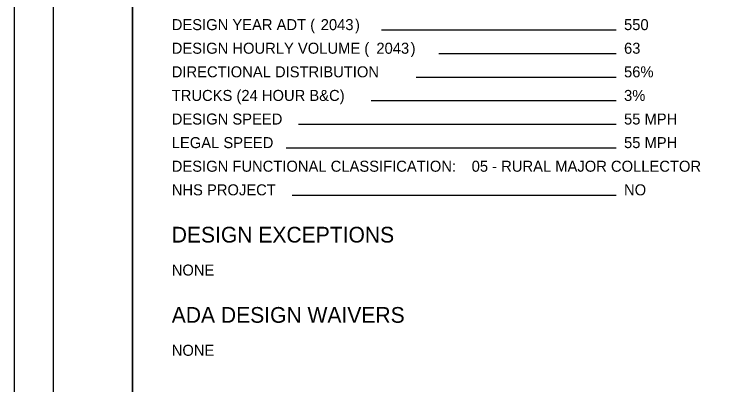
# Model space of a CAD drawing. Extents: x -6.4 to 34, y -1.2 to 22.
# Drawn here: x 0 to 9.02, y 5.69 to 10.4 of the extents above; entities that cross this region are included whole.
import ezdxf

# ---------------------------------------------------------------- set-up
doc = ezdxf.new("R2010")
doc.units = 0
for name, color, linetype in [('GM_X_County', 7, 'Continuous'), ('GM_X_Section', 7, 'Continuous'), ('GM_X_Township', 7, 'Continuous')]:
    doc.layers.add(name, color=color, linetype=linetype)

msp = doc.modelspace()

# ---------------------------------------------------------------- linework, layer by layer
at = {"layer": 'GM_X_County'}
for points in [[(0.5, 21.5), (1.5, 21.5), (1.5, 0.5), (0.5, 0.5)], [(1.5, 21.5), (33.5, 21.5), (33.5, 0.5), (1.5, 0.5)]]:
    msp.add_lwpolyline(points, close=True, dxfattribs=at)
at = {"layer": 'GM_X_Section'}
msp.add_lwpolyline([(0, 0), (34, 0), (34, 22), (0, 22)], close=True, dxfattribs=at)
at = {"layer": 'GM_X_Township'}
for p, q in [((7.6424, 10.2), (4.6648, 10.2)), ((7.6424, 9.9), (5.3908, 9.9)), ((7.6424, 9.6), (5.1044, 9.6)), ((7.6424, 9.3), (4.5314, 9.3)), ((7.6424, 9), (3.6091, 9)), ((7.6424, 8.7), (3.4544, 8.7)), ((7.6424, 8.1), (3.5298, 8.1))]:
    msp.add_line(p, q, dxfattribs=at)

# ---------------------------------------------------------------- texts
for s, height, p in [('DESIGN YEAR ADT (', 0.14, (2, 10.2)), ('2043', 0.14, (3.8914, 10.2)), (')', 0.14, (4.3263, 10.2)), ('550', 0.14, (7.7424, 10.2)), ('DESIGN HOURLY VOLUME (', 0.14, (2, 9.9)), ('2043', 0.14, (4.598, 9.9)), (')', 0.14, (5.0329, 9.9)), ('63', 0.14, (7.7424, 9.9)), ('DIRECTIONAL DISTRIBUTION', 0.14, (2, 9.6)), ('56%', 0.14, (7.7424, 9.6)), ('TRUCKS (24 HOUR B&C)', 0.14, (2, 9.3)), ('3%', 0.14, (7.7424, 9.3)), ('DESIGN SPEED', 0.14, (2, 9)), ('55 MPH', 0.14, (7.7424, 9)), ('LEGAL SPEED', 0.14, (2, 8.7)), ('55 MPH', 0.14, (7.7424, 8.7)), ('DESIGN FUNCTIONAL CLASSIFICATION: ', 0.14, (2, 8.4)), ('05 - RURAL MAJOR COLLECTOR', 0.14, (5.8079, 8.4)), ('NHS PROJECT', 0.14, (2, 8.1)), ('NO', 0.14, (7.7424, 8.1)), ('DESIGN EXCEPTIONS', 0.2, (2, 7.5)), ('NONE', 0.14, (2, 7.08)), ('ADA DESIGN WAIVERS', 0.2, (2, 6.48)), ('NONE', 0.14, (2, 6.06))]:
    msp.add_text(s, height=height, dxfattribs=at).set_placement(p)

doc.saveas('drawing.dxf')
